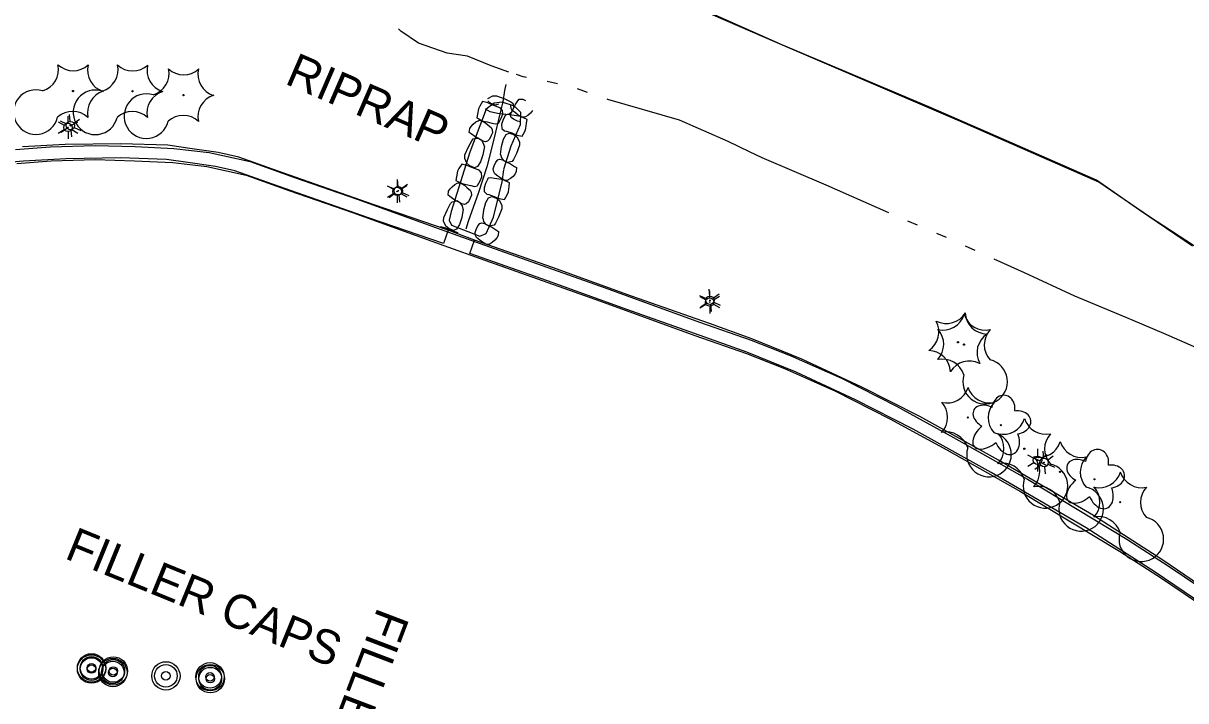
# Model space of a CAD drawing. Extents: x 588843 to 2552415, y 180129 to 269402.
# Drawn here: x 593491.7 to 593696.8, y 185491.8 to 185611.3 of the extents above; entities that cross this region are included whole.
import ezdxf

# ---------------------------------------------------------------- set-up
doc = ezdxf.new("R2010")
doc.units = 0
for name, color, linetype in [('Default', 7, 'Continuous'), ('E_DRN_RipRap', 7, 'Continuous'), ('E_DRN_RipRap_Text', 7, 'Continuous'), ('E_DWY', 7, 'Continuous'), ('E_LAND_Vegetation', 7, 'Continuous'), ('E_LTG', 7, 'Continuous'), ('E_MISCPROP', 7, 'Continuous'), ('E_MISCPROP_Text', 7, 'Continuous'), ('E_RDWY', 7, 'Continuous'), ('E_WTR_P', 7, 'Continuous')]:
    doc.layers.add(name, color=color, linetype=linetype)

# ---------------------------------------------------------------- blocks, each defined once
blk = doc.blocks.new('LPOL')
at = {"layer": 'Default'}
for p, q in [((-4, 0), (-1.5, 0)), ((-0.75, 1.3), (-2, 3.46)), ((0.75, 1.3), (2, 3.46)), ((1.5, 0), (4, 0)), ((-2, -3.46), (-0.75, -1.3)), ((2, -3.46), (0.75, -1.3))]:
    blk.add_line(p, q, dxfattribs=at)
for radius in [1.5, 1.5, 1.5, 0.125]:
    blk.add_circle((0, 0), radius, dxfattribs=at)
blk = doc.blocks.new('CTRE')
at = {"layer": 'Default'}
blk.add_circle((0, 0), 0.223, dxfattribs=at)
for centre, start, end in [((-11.97, 8.96), 280.2067, 5.9716), ((1.81, 14.92), 220.2113, 305.9762), ((13.83, 5.89), 160.2113, 245.9762), ((-13.83, -5.9), 340.2113, 65.9762), ((12.03, -9.04), 185.9272, 100.2511), ((-1.81, -14.93), 40.2113, 125.9762)]:
    blk.add_arc(centre, 7.87, start, end, dxfattribs=at)
blk = doc.blocks.new('RIPRT')
at = {"layer": 'E_DRN_RipRap_Text'}
blk.add_text('RIPRAP', height=12, dxfattribs=at).set_placement((-0.14, -3.59))
blk = doc.blocks.new('FILO')
at = {"layer": 'E_MISCPROP'}
for radius in [5, 4, 1.5]:
    blk.add_circle((0, 0), radius, dxfattribs=at)
blk = doc.blocks.new('FILT')
at = {"layer": 'E_MISCPROP_Text'}
blk.add_text('FILLER CAPS', height=12, dxfattribs=at).set_placement((12, -4))
blk = doc.blocks.new('FILT_6')
at = {"layer": 'E_MISCPROP_Text'}
blk.add_text('FILLER CAP', height=39.37, dxfattribs=at).set_placement((32.8, -19.7))
blk = doc.blocks.new('FILO_1')
at = {"layer": 'E_MISCPROP'}
for radius in [16.4, 13.1, 4.92]:
    blk.add_circle((0, 0), radius, dxfattribs=at)
blk = doc.blocks.new('LPOL_4')
at = {"layer": 'E_LTG'}
for p, q in [((-13.1, 0), (-4.9, 0)), ((-2.5, 4.3), (-6.6, 11.4)), ((2.5, 4.3), (6.6, 11.4)), ((4.9, 0), (13.1, 0)), ((-6.6, -11.4), (-2.5, -4.3)), ((6.6, -11.4), (2.5, -4.3))]:
    blk.add_line(p, q, dxfattribs=at)
for radius in [4.92, 4.92, 4.92, 0.41]:
    blk.add_circle((0, 0), radius, dxfattribs=at)
blk = doc.blocks.new('CTRE_4')
at = {"layer": 'E_LAND_Vegetation'}
blk.add_circle((0, 0), 0.733, dxfattribs=at)
for centre, start, end in [((-39.3, 29.4), 280.2067, 5.9716), ((5.9, 49), 220.2113, 305.9762), ((45.4, 19.3), 160.2113, 245.9762), ((-45.4, -19.3), 340.2113, 65.9762), ((39.5, -29.6), 100.2511, 185.9272), ((-5.9, -49), 40.2113, 125.9762)]:
    blk.add_arc(centre, 25.8, start, end, dxfattribs=at)
blk = doc.blocks.new('DTRE_4')
at = {"layer": 'E_LAND_Vegetation'}
blk.add_circle((-0.6, 0), 0.601, dxfattribs=at)
for centre, major_axis, ratio in [((-6.1, 17.5), (4.5, -16.3), 0.782863), ((-19.3, 0.5), (16.2, -0.4), 0.832022), ((13.3, 9), (-17.3, -9.6), 0.691916), ((-8.2, -17.2), (5.9, 15.9), 0.716896), ((11.6, -12.2), (-16.4, 15), 0.560249)]:
    blk.add_ellipse(centre, major_axis=major_axis, ratio=ratio, start_param=1.570796, end_param=4.712389, dxfattribs=at)

msp = doc.modelspace()

# ---------------------------------------------------------------- linework, layer by layer
at = {"layer": 'E_DRN_RipRap'}
for p, q in [((593573.68, 185598.03), (593574.53, 185598.47)), ((593574.53, 185598.47), (593575.16, 185598.49)), ((593575.16, 185598.49), (593576.64, 185597.93)), ((593572.01, 185596.19), (593571.86, 185595.23)), ((593572.26, 185596.68), (593572.01, 185596.19)), ((593572.74, 185597.46), (593572.26, 185596.68)), ((593573.66, 185597.23), (593572.74, 185597.46)), ((593574.08, 185595.66), (593573.24, 185596.13)), ((593574.55, 185596.83), (593573.66, 185597.23)), ((593574.18, 185597.14), (593573.67, 185597.59)), ((593574.99, 185596.81), (593574.18, 185597.14)), ((593575.48, 185596.49), (593574.55, 185596.83)), ((593575.55, 185597.03), (593574.99, 185596.81)), ((593575.84, 185596.39), (593575.48, 185596.49)), ((593576.26, 185595.92), (593575.84, 185596.39)), ((593576.64, 185597.93), (593577.72, 185597.42)), ((593577.77, 185596.24), (593577.7, 185596.77)), ((593577.72, 185597.42), (593578.06, 185597.19)), ((593577.77, 185595.47), (593578.49, 185596.89)), ((593577.95, 185595.9), (593577.77, 185596.24)), ((593577.88, 185595.68), (593578.24, 185596.37)), ((593578.06, 185597.19), (593578.24, 185596.37)), ((593578.49, 185596.89), (593578.93, 185597.61)), ((593578.93, 185597.61), (593579.16, 185597.92)), ((593579.16, 185597.92), (593579.85, 185597.89)), ((593579.85, 185597.89), (593580.28, 185597.67)), ((593571.54, 185593.87), (593571.94, 185594.09)), ((593571.86, 185595.23), (593571.73, 185594.6)), ((593571.73, 185594.6), (593572.86, 185594.02)), ((593571.94, 185594.09), (593572.11, 185594.17)), ((593572.11, 185594.17), (593572.66, 185594.09)), ((593572.66, 185594.09), (593573.23, 185593.73)), ((593572.86, 185594.02), (593573.53, 185593.88)), ((593575.38, 185595.34), (593574.08, 185595.66)), ((593576.85, 185595.16), (593575.38, 185595.34)), ((593575.57, 185593.71), (593576.02, 185594.54)), ((593576.02, 185594.54), (593576.28, 185595.24)), ((593576.29, 185594.14), (593576.07, 185593.42)), ((593576.28, 185595.24), (593576.26, 185595.92)), ((593576.69, 185594.99), (593576.29, 185594.14)), ((593576.8, 185595.09), (593576.69, 185594.99)), ((593577.26, 185595.21), (593576.8, 185595.09)), ((593576.85, 185595.16), (593577.4, 185595.3)), ((593577.88, 185595.09), (593577.26, 185595.21)), ((593577.4, 185595.3), (593577.88, 185595.68)), ((593577.67, 185594.99), (593577.77, 185595.47)), ((593577.8, 185594.68), (593577.67, 185594.99)), ((593578.2, 185594.34), (593577.8, 185594.68)), ((593578.74, 185594.93), (593577.88, 185595.09)), ((593578.51, 185595.47), (593577.95, 185595.9)), ((593578.88, 185594.04), (593578.2, 185594.34)), ((593579.03, 185595.09), (593578.51, 185595.47)), ((593579.41, 185594.82), (593578.74, 185594.93)), ((593579.4, 185593.88), (593578.88, 185594.04)), ((593579.61, 185594.77), (593579.03, 185595.09)), ((593580.58, 185594.31), (593579.41, 185594.82)), ((593580.17, 185594.72), (593579.61, 185594.77)), ((593580.33, 185594.8), (593580.17, 185594.72)), ((593580.72, 185595.04), (593580.33, 185594.8)), ((593580.48, 185593.67), (593580.58, 185594.31)), ((593581.19, 185595.45), (593580.72, 185595.04)), ((593581.52, 185595.87), (593581.19, 185595.45)), ((593570.39, 185592), (593570.45, 185592.69)), ((593570.69, 185591.76), (593570.39, 185592)), ((593570.45, 185592.69), (593570.7, 185593.09)), ((593570.7, 185593.09), (593571.05, 185593.49)), ((593571.05, 185593.49), (593571.54, 185593.87)), ((593573.23, 185593.73), (593573.73, 185593.32)), ((593573.53, 185593.88), (593574.37, 185593.67)), ((593573.73, 185593.32), (593574.27, 185592.87)), ((593574.27, 185592.87), (593574.42, 185592.51)), ((593574.47, 185591.98), (593574.27, 185591.48)), ((593574.37, 185593.67), (593574.98, 185593.52)), ((593574.42, 185592.51), (593574.47, 185591.98)), ((593574.98, 185593.52), (593575.46, 185593.61)), ((593575.46, 185593.61), (593575.57, 185593.71)), ((593576.07, 185593.42), (593576.12, 185592.74)), ((593576.12, 185592.74), (593576.57, 185592.29)), ((593576.57, 185592.29), (593576.93, 185592.22)), ((593576.93, 185592.22), (593577.88, 185591.93)), ((593579.72, 185591.39), (593580.16, 185592.2)), ((593580.16, 185592.2), (593580.38, 185592.7)), ((593580.38, 185592.7), (593580.48, 185593.67)), ((593570.24, 185589.51), (593570.81, 185590.55)), ((593571.39, 185591.28), (593570.69, 185591.76)), ((593570.81, 185590.55), (593571.06, 185590.87)), ((593571.06, 185590.87), (593571.9, 185591)), ((593572.78, 185590.48), (593571.39, 185591.28)), ((593572.57, 185590.61), (593571.9, 185591)), ((593572.92, 185590.1), (593572.57, 185590.61)), ((593573.26, 185590.35), (593572.78, 185590.48)), ((593573.04, 185589.55), (593572.92, 185590.1)), ((593573.57, 185590.46), (593573.26, 185590.35)), ((593573.94, 185590.83), (593573.57, 185590.46)), ((593574.27, 185591.48), (593573.94, 185590.83)), ((593576.09, 185589.56), (593576.42, 185590.84)), ((593576.42, 185590.84), (593576.89, 185591.67)), ((593576.89, 185591.67), (593577.44, 185591.92)), ((593577.44, 185591.92), (593578.27, 185591.64)), ((593577.88, 185591.93), (593578.79, 185591.57)), ((593578.27, 185591.64), (593578.8, 185591.22)), ((593578.79, 185591.57), (593579.72, 185591.39)), ((593578.8, 185591.22), (593579.25, 185590.37)), ((593579.25, 185590.37), (593579.27, 185589.75)), ((593569.58, 185587.45), (593569.59, 185588.08)), ((593569.59, 185588.08), (593570.24, 185589.51)), ((593572.78, 185588.1), (593572.38, 185586.83)), ((593573.04, 185589.55), (593572.78, 185588.1)), ((593575.91, 185588.11), (593576.09, 185589.56)), ((593575.91, 185588.11), (593576.06, 185587.56)), ((593578.7, 185588.3), (593578.19, 185587.24)), ((593579.27, 185589.75), (593578.7, 185588.3)), ((593569.04, 185586.45), (593568.56, 185585.66)), ((593569.96, 185586.22), (593569.04, 185586.45)), ((593569.97, 185586.58), (593569.58, 185587.45)), ((593570.85, 185585.82), (593569.96, 185586.22)), ((593570.48, 185586.13), (593569.97, 185586.58)), ((593571.29, 185585.8), (593570.48, 185586.13)), ((593571.78, 185585.47), (593570.85, 185585.82)), ((593571.86, 185586.02), (593571.29, 185585.8)), ((593572.38, 185586.83), (593571.86, 185586.02)), ((593574.62, 185585.61), (593574.79, 185586.12)), ((593574.79, 185586.12), (593575.08, 185586.79)), ((593575.08, 185586.79), (593575.44, 185587.18)), ((593575.44, 185587.18), (593575.74, 185587.31)), ((593575.74, 185587.31), (593576.23, 185587.2)), ((593576.06, 185587.56), (593576.44, 185587.09)), ((593576.23, 185587.2), (593577.66, 185586.48)), ((593576.44, 185587.09), (593577.13, 185586.73)), ((593577.97, 185586.9), (593577.13, 185586.73)), ((593577.66, 185586.48), (593578.38, 185586.03)), ((593578.19, 185587.24), (593577.97, 185586.9)), ((593578.38, 185586.03), (593578.7, 185585.81)), ((593578.7, 185585.81), (593578.67, 185585.12)), ((593568.15, 185584.2), (593568.02, 185583.56)), ((593568.31, 185585.17), (593568.15, 185584.2)), ((593568.56, 185585.66), (593568.31, 185585.17)), ((593572.14, 185585.38), (593571.78, 185585.47)), ((593572.56, 185584.91), (593572.14, 185585.38)), ((593572.31, 185583.51), (593572.58, 185584.22)), ((593572.58, 185584.22), (593572.56, 185584.91)), ((593573.63, 185583.85), (593573.22, 185582.99)), ((593573.73, 185583.93), (593573.62, 185583.83)), ((593574.19, 185584.04), (593573.73, 185583.93)), ((593574.81, 185583.92), (593574.19, 185584.04)), ((593574.7, 185585.08), (593574.62, 185585.61)), ((593574.87, 185584.73), (593574.7, 185585.08)), ((593575.66, 185583.77), (593574.81, 185583.92)), ((593575.43, 185584.31), (593574.87, 185584.73)), ((593575.95, 185583.93), (593575.43, 185584.31)), ((593576.34, 185583.66), (593575.66, 185583.77)), ((593576.54, 185583.6), (593575.95, 185583.93)), ((593577.65, 185583.88), (593577.26, 185583.64)), ((593578.12, 185584.28), (593577.65, 185583.88)), ((593578.45, 185584.7), (593578.12, 185584.28)), ((593578.67, 185585.12), (593578.45, 185584.7)), ((593566.74, 185581.64), (593566.99, 185582.05)), ((593566.99, 185582.05), (593567.34, 185582.45)), ((593567.34, 185582.45), (593567.83, 185582.83)), ((593567.83, 185582.83), (593568.23, 185583.05)), ((593568.02, 185583.56), (593569.15, 185582.99)), ((593568.23, 185583.05), (593568.4, 185583.13)), ((593568.4, 185583.13), (593568.95, 185583.05)), ((593568.95, 185583.05), (593569.52, 185582.7)), ((593569.15, 185582.99), (593569.82, 185582.84)), ((593569.52, 185582.7), (593570.02, 185582.28)), ((593569.82, 185582.84), (593570.67, 185582.64)), ((593570.02, 185582.28), (593570.56, 185581.83)), ((593570.56, 185581.83), (593570.71, 185581.47)), ((593570.67, 185582.64), (593571.28, 185582.49)), ((593571.28, 185582.49), (593571.75, 185582.58)), ((593571.75, 185582.58), (593571.86, 185582.68)), ((593571.86, 185582.68), (593572.31, 185583.51)), ((593573.22, 185582.99), (593572.98, 185582.27)), ((593572.98, 185582.27), (593573.03, 185581.58)), ((593577.5, 185583.15), (593576.34, 185583.66)), ((593577.1, 185583.55), (593576.54, 185583.6)), ((593577.26, 185583.64), (593577.1, 185583.55)), ((593577.29, 185581.52), (593577.41, 185582.49)), ((593577.41, 185582.5), (593577.5, 185583.15)), ((593566.67, 185580.95), (593566.74, 185581.64)), ((593566.97, 185580.71), (593566.67, 185580.95)), ((593567.67, 185580.22), (593566.97, 185580.71)), ((593567.09, 185579.49), (593567.34, 185579.81)), ((593567.34, 185579.81), (593568.18, 185579.94)), ((593569.06, 185579.43), (593567.67, 185580.22)), ((593568.85, 185579.55), (593568.18, 185579.94)), ((593570.22, 185579.77), (593569.85, 185579.41)), ((593570.56, 185580.43), (593570.22, 185579.77)), ((593570.75, 185580.94), (593570.56, 185580.43)), ((593570.71, 185581.47), (593570.75, 185580.94)), ((593573.03, 185581.58), (593573.47, 185581.12)), ((593573.3, 185579.65), (593573.78, 185580.49)), ((593573.47, 185581.12), (593573.83, 185581.05)), ((593573.78, 185580.49), (593574.34, 185580.74)), ((593573.83, 185581.05), (593574.78, 185580.75)), ((593574.34, 185580.74), (593575.16, 185580.45)), ((593574.78, 185580.75), (593575.68, 185580.38)), ((593575.16, 185580.45), (593575.69, 185580.02)), ((593575.68, 185580.38), (593576.61, 185580.2)), ((593575.69, 185580.02), (593576.12, 185579.16)), ((593576.61, 185580.2), (593577.06, 185581.02)), ((593577.06, 185581.02), (593577.29, 185581.52)), ((593565.87, 185577.02), (593566.52, 185578.45)), ((593566.52, 185578.45), (593567.09, 185579.49)), ((593569.2, 185579.05), (593568.85, 185579.55)), ((593569.54, 185579.29), (593569.06, 185579.43)), ((593569.32, 185578.49), (593569.06, 185577.04)), ((593569.32, 185578.49), (593569.2, 185579.05)), ((593569.85, 185579.41), (593569.54, 185579.29)), ((593572.75, 185576.9), (593572.95, 185578.36)), ((593572.95, 185578.36), (593573.3, 185579.65)), ((593576.13, 185578.54), (593575.55, 185577.07)), ((593576.12, 185579.16), (593576.13, 185578.54)), ((593565.86, 185576.4), (593565.87, 185577.02)), ((593566.25, 185575.52), (593565.86, 185576.4)), ((593568.66, 185575.78), (593568.14, 185574.97)), ((593569.06, 185577.04), (593568.66, 185575.78)), ((593571.6, 185574.89), (593571.91, 185575.56)), ((593571.91, 185575.56), (593572.26, 185575.95)), ((593572.26, 185575.95), (593572.57, 185576.08)), ((593572.57, 185576.08), (593573.06, 185575.97)), ((593572.75, 185576.9), (593572.89, 185576.34)), ((593572.89, 185576.34), (593573.27, 185575.86)), ((593573.06, 185575.97), (593574.48, 185575.23)), ((593573.27, 185575.86), (593573.96, 185575.49)), ((593574.79, 185575.66), (593573.96, 185575.49)), ((593575.03, 185576), (593574.79, 185575.66)), ((593575.55, 185577.07), (593575.03, 185576)), ((593566.24, 185575.16), (593565.32, 185575.39)), ((593567.13, 185574.76), (593566.24, 185575.16)), ((593566.76, 185575.07), (593566.25, 185575.52)), ((593567.57, 185574.74), (593566.76, 185575.07)), ((593568.06, 185574.42), (593567.13, 185574.76)), ((593568.14, 185574.97), (593567.57, 185574.74)), ((593568.42, 185574.32), (593568.06, 185574.42)), ((593571.43, 185574.37), (593571.6, 185574.89)), ((593571.49, 185573.84), (593571.43, 185574.37)), ((593571.66, 185573.49), (593571.49, 185573.84)), ((593574.48, 185575.23), (593575.2, 185574.78)), ((593575.2, 185574.78), (593575.51, 185574.55)), ((593575.47, 185573.86), (593575.24, 185573.44)), ((593575.51, 185574.55), (593575.47, 185573.86)), ((593572.22, 185573.05), (593571.66, 185573.49)), ((593572.74, 185572.66), (593572.22, 185573.05)), ((593573.32, 185572.33), (593572.74, 185572.66)), ((593573.88, 185572.28), (593573.32, 185572.33)), ((593574.04, 185572.37), (593573.88, 185572.28)), ((593574.44, 185572.61), (593574.04, 185572.37)), ((593574.91, 185573.01), (593574.44, 185572.61)), ((593575.24, 185573.44), (593574.91, 185573.01))]:
    msp.add_line(p, q, dxfattribs=at)
msp.add_lwpolyline([(593576.5, 185585.52), (593577.76, 185589.66), (593579.44, 185593.4), (593579.49, 185595.52), (593578.34, 185596.64), (593576.2, 185597.36), (593574.75, 185597.18), (593573.39, 185596.14), (593570.49, 185588.53), (593567.2, 185578.1), (593566.83, 185576.55), (593567.26, 185575.64), (593572.23, 185573.7), (593573.34, 185574.2), (593574.63, 185577.09), (593575.65, 185581.16), (593576.16, 185583.32), (593576.48, 185585.45)], dxfattribs=at)
at = {"layer": 'E_DWY'}
for points in [[(593566.67, 185574.78), (593553.42, 185579.32), (593537.5, 185584.92), (593529.73, 185587.65), (593526.05, 185588.49), (593521.08, 185589.18), (593517.19, 185589.75), (593508.89, 185590.04), (593499.1, 185589.89), (593491.54, 185589.46)], [(593490.32, 185589.04), (593496.45, 185589.5), (593504.37, 185589.73), (593511.41, 185589.54), (593518.27, 185589.2), (593524.49, 185588.5), (593531.69, 185586.88), (593539.54, 185584.06), (593550.59, 185580.25), (593566.72, 185574.45), (593573.97, 185571.85), (593594.37, 185564.62), (593611.02, 185558.58), (593620.15, 185555.38), (593626.99, 185552.69), (593636.09, 185548.67), (593645.75, 185543.72), (593655.84, 185538.23), (593668.9, 185530.85), (593686.44, 185520.31), (593693.91, 185515.46), (593702.15, 185509.9)], [(593565.86, 185572.42), (593552.6, 185576.96), (593536.67, 185582.56), (593529.04, 185585.25), (593525.6, 185586.03), (593520.73, 185586.7), (593516.97, 185587.25), (593508.86, 185587.54), (593499.19, 185587.39), (593491.72, 185586.97), (593484.75, 185586.34)], [(593490.56, 185586.55), (593496.58, 185587), (593504.37, 185587.23), (593511.31, 185587.04), (593518.07, 185586.7), (593524.07, 185586.03), (593530.99, 185584.47), (593538.72, 185581.7), (593549.76, 185577.9), (593565.87, 185572.1), (593573.13, 185569.5), (593593.53, 185562.27), (593610.18, 185556.22), (593619.28, 185553.04), (593626.03, 185550.39), (593635.01, 185546.41), (593644.59, 185541.51), (593654.63, 185536.04), (593667.64, 185528.69), (593685.12, 185518.19), (593692.53, 185513.38), (593700.69, 185507.86)], [(593570.46, 185570.69), (593571.3, 185573.05), (593566.67, 185574.78), (593565.86, 185572.42)], [(593780.96, 185417.08), (593776.04, 185427.16), (593771.25, 185435.1), (593766.16, 185443.32), (593762.33, 185449.04), (593758.69, 185454.46), (593752.87, 185462.33), (593743.93, 185472.37), (593734.35, 185482.42), (593725.38, 185491.19), (593717.41, 185498.54), (593711.09, 185503.67), (593703.12, 185509.55), (593692.76, 185516.55), (593680.51, 185524.43), (593663.74, 185534.21), (593649.9, 185541.92), (593639.65, 185547.08), (593629.09, 185552.01), (593620.26, 185555.6), (593612.76, 185558.3), (593599, 185563.16), (593585.05, 185568.18), (593571.3, 185573.05)], [(593778.71, 185415.98), (593773.84, 185425.96), (593769.11, 185433.8), (593764.06, 185441.97), (593760.26, 185447.65), (593756.65, 185453.02), (593750.93, 185460.75), (593742.09, 185470.68), (593732.57, 185480.67), (593723.66, 185489.38), (593715.77, 185496.65), (593709.56, 185501.69), (593701.67, 185507.5), (593691.39, 185514.46), (593679.21, 185522.29), (593662.5, 185532.04), (593648.73, 185539.71), (593638.56, 185544.83), (593628.09, 185549.71), (593619.36, 185553.26), (593611.92, 185555.94), (593598.16, 185560.81), (593584.21, 185565.83), (593570.46, 185570.69)]]:
    msp.add_lwpolyline(points, dxfattribs=at)
at = {"layer": 'E_RDWY'}
for points in [[(593805.06, 185499.36), (593796.08, 185505.71), (593778.99, 185517.59), (593765.58, 185526.62), (593750.52, 185536.77), (593736.83, 185546.06), (593725.23, 185553.81), (593714.32, 185561.29), (593702.05, 185569.53), (593690.43, 185577.12), (593681.49, 185583.28), (593656.92, 185594.04), (593626.9, 185606.88), (593604.28, 185616.72), (593578.06, 185627.87), (593554.17, 185638.2), (593528.97, 185649.12), (593509.99, 185657.21), (593506.4, 185658.17), (593479.1, 185664.49), (593455.91, 185669.88), (593438.41, 185673.77)], [(593698.01, 185571.94), (593688.62, 185578.29), (593681.05, 185583.59), (593675.17, 185586.22), (593662.43, 185591.77), (593651.91, 185596.35), (593640.5, 185601.19), (593625.4, 185607.53), (593613.63, 185612.79), (593601.92, 185617.92), (593588.88, 185623.58), (593576.37, 185628.83), (593565.9, 185633.32), (593550.87, 185639.79), (593539.52, 185644.78), (593529.63, 185649.16), (593515.76, 185655.12), (593508.93, 185658), (593506.71, 185658.75), (593494.07, 185661.19), (593479.18, 185664.59), (593467.68, 185667.38), (593453.78, 185670.37), (593447.3, 185671.82)]]:
    msp.add_lwpolyline(points, dxfattribs=at)
at = {"layer": 'E_WTR_P'}
for points in [[(593577.36, 185602.68), (593574.25, 185603.8), (593570.09, 185605.49), (593566.46, 185606), (593561.41, 185607.79), (593558.3, 185609.89), (593557.91, 185610.3)], [(593580.49, 185601.72), (593579.88, 185601.84), (593578.71, 185602.23)], [(593576.86, 185600.48), (593576.6, 185599.43), (593576.32, 185597.41), (593575.75, 185595.33), (593574.8, 185591.05), (593573.46, 185585.97), (593572.02, 185581.43), (593570.19, 185576.29), (593569.8, 185574.97)], [(593585.92, 185600.62), (593584.11, 185600.98)], [(593591.25, 185599.09), (593589.5, 185599.7)], [(593619.84, 185588.63), (593616.08, 185590.45), (593607.5, 185594.16), (593594.82, 185597.84), (593594.74, 185597.87)], [(593644.39, 185577.85), (593633.35, 185582.7), (593622.04, 185587.57), (593619.84, 185588.63)], [(593649.49, 185575.67), (593647.79, 185576.4)], [(593654.59, 185573.49), (593652.89, 185574.21)], [(593659.64, 185571.2), (593657.96, 185571.96)], [(593687.54, 185558.84), (593686.39, 185559.33), (593677.23, 185563.16), (593668.36, 185567.26), (593663.01, 185569.68)], [(593711.91, 185547.68), (593704.08, 185551.61), (593697.65, 185554.48), (593692.94, 185556.53), (593687.54, 185558.84)]]:
    msp.add_lwpolyline(points, dxfattribs=at)

# ---------------------------------------------------------------- block references
at = {"layer": 'E_DRN_RipRap_Text', "xscale": 0.49999999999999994, "yscale": 0.5000000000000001, "rotation": -23.368950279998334}
msp.add_blockref('RIPRT', (593538.41, 185602.31), dxfattribs=at)
at = {"layer": 'E_LAND_Vegetation'}
for name, p, xscale, yscale, rotation in [('CTRE', (593500.45, 185599.32), 0.49999999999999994, 0.5, -113.47546916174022), ('CTRE', (593510.96, 185599.29), 0.49999999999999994, 0.5, -113.47546916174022), ('CTRE', (593519.95, 185598.61), 0.49999999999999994, 0.5, -113.47546916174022), ('CTRE', (593657.68, 185554.6), 0.49999999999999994, 0.5000000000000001, -23.368950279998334), ('CTRE_4', (593656.61, 185555.02), 0.1524003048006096, 0.1524003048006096, -97.36026881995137), ('CTRE', (593658.36, 185541.75), 0.49999999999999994, 0.5000000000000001, -23.368950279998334), ('DTRE_4', (593664.15, 185540.3), 0.1524003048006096, 0.1524003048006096, -97.36026881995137), ('CTRE', (593668.32, 185536.23), 0.49999999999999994, 0.5000000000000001, -23.368950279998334), ('CTRE', (593674.62, 185532.16), 0.49999999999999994, 0.5000000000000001, -23.368950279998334), ('DTRE_4', (593680.69, 185530.75), 0.1524003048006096, 0.1524003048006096, -97.36026881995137), ('CTRE', (593685.24, 185526.81), 0.49999999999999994, 0.5000000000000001, -23.368950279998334)]:
    msp.add_blockref(name, p, dxfattribs=dict(at, xscale=xscale, yscale=yscale, rotation=rotation))
at = {"layer": 'E_LTG'}
for name, p, xscale, yscale, rotation in [('LPOL', (593499.57, 185592.91), 0.5000000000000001, 0.5, -89.67337617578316), ('LPOL_4', (593499.99, 185593.22), 0.1524003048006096, 0.15240030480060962, -84.36014555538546), ('LPOL_4', (593557.86, 185581.74), 0.1524003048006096, 0.15240030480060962, -84.36014555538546), ('LPOL', (593557.65, 185581.63), 0.5000000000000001, 0.5, -89.67337617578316), ('LPOL_4', (593612.85, 185562.41), 0.1524003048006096, 0.15240030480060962, -84.36014555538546), ('LPOL', (593612.8, 185562.11), 0.5000000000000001, 0.5, -89.67337617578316), ('LPOL', (593670.64, 185534.19), 0.5000000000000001, 0.5, -89.67337617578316), ('LPOL_4', (593671.8, 185533.8), 0.1524003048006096, 0.15240030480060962, -84.36014555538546)]:
    msp.add_blockref(name, p, dxfattribs=dict(at, xscale=xscale, yscale=yscale, rotation=rotation))
at = {"layer": 'E_MISCPROP'}
for name, p, xscale, yscale, rotation in [('FILO', (593503.72, 185497.58), 0.49999999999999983, 0.49999999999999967, -22.215816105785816), ('FILO_1', (593503.72, 185497.37), 0.1524003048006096, 0.15240030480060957, -110.8554466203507), ('FILO_1', (593507.49, 185496.76), 0.1524003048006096, 0.15240030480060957, -110.8554466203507), ('FILO', (593507.57, 185497.04), 0.49999999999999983, 0.49999999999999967, -22.215816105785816), ('FILO_1', (593516.85, 185496.17), 0.1524003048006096, 0.15240030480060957, -110.8554466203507), ('FILO', (593524.63, 185496.01), 0.49999999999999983, 0.49999999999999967, -22.215816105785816), ('FILO_1', (593524.68, 185495.67), 0.1524003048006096, 0.15240030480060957, -110.8554466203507)]:
    msp.add_blockref(name, p, dxfattribs=dict(at, xscale=xscale, yscale=yscale, rotation=rotation))
at = {"layer": 'E_MISCPROP_Text'}
for name, p, xscale, yscale, rotation in [('FILT', (593493.98, 185521.09), 0.49999999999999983, 0.49999999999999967, -22.215816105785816), ('FILT_6', (593558.87, 185512.04), 0.1524003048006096, 0.15240030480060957, -110.8554466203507)]:
    msp.add_blockref(name, p, dxfattribs=dict(at, xscale=xscale, yscale=yscale, rotation=rotation))

doc.saveas('drawing.dxf')
